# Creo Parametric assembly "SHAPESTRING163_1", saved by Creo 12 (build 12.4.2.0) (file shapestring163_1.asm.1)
Units: Custom; MM, KILOGRAM, SECS

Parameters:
  PTC_WM_ITERATION = "0"
  PTC_WM_VERSION = "-.0"
  PTC_WM_LIFECYCLE_STATE = "In Work"
  PTC_WM_LIFECYCLE = "MO_CADDocument"
  PTC_WM_CREATED_BY = "Maximilian Roepper (Z0017RMS: MO)"
  PTC_WM_CREATED_ON = "18-Sep-26 11:36:42 AM"
  PTC_WM_MODIFIED_BY = "Maximilian Roepper (Z0017RMS: MO)"
  PTC_WM_MODIFIED_ON = "18-Sep-26 11:36:46 AM"
  PDMLINKNUMBER = "PDM000071454995"
  PTC_WM_NUMBER = "PDM000071454995"

Other parameters: WEIGHT, WEIGHT_FACTOR, WEIGHT_ADD, MC_ERRORS, SUPPLIER

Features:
  1. coordinate system
  2. imported feature
  3. component "SHAPESTRING078_1"
  4. component "SHAPESTRING159_1"
  5. component "SHAPESTRING160_1"
  6. component "SHAPESTRING161_1"
  7. component "SHAPESTRING162_1"

Other named items: DRW_VIEW_ORG, ROUGH-GROB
